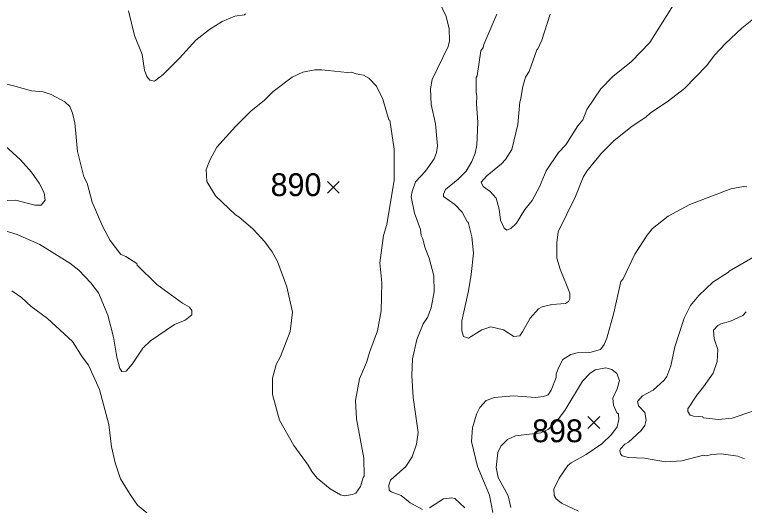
# Model space of a CAD drawing. Extents: x 265.7 to 292.1, y 7676.2 to 7704.2.
# Drawn here: x 270.846 to 273.408, y 7685.609 to 7687.332 of the extents above; entities that cross this region are included whole.
import ezdxf
from ezdxf.enums import TextEntityAlignment as Align

# ---------------------------------------------------------------- set-up
doc = ezdxf.new("R2010")
doc.units = 0
doc.header["$LTSCALE"] = 0.032
doc.layers.add('2', color=7, linetype='Continuous', lineweight=13)
doc.layers.add('21', color=7, linetype='Continuous', lineweight=25)
doc.layers.add('61', color=7, linetype='Continuous')

msp = doc.modelspace()

# ---------------------------------------------------------------- linework, layer by layer
at = {"layer": '2'}
for points in [[(272.2789, 7685.5938), (272.235, 7685.6178), (272.2031, 7685.6433), (272.1688, 7685.6561), (272.1616, 7685.6625), (272.1608, 7685.68), (272.1664, 7685.6968), (272.2199, 7685.7454), (272.2422, 7685.779), (272.2574, 7685.8236), (272.263, 7685.8651), (272.2454, 7685.988), (272.2414, 7686.0646), (272.2438, 7686.1237), (272.259, 7686.1907), (272.2805, 7686.2466), (272.2957, 7686.2689), (272.3084, 7686.3024), (272.3196, 7686.3583), (272.318, 7686.4141), (272.3021, 7686.4772), (272.2869, 7686.5147), (272.2797, 7686.545), (272.2741, 7686.5562), (272.2709, 7686.5769), (272.2502, 7686.6344), (272.239, 7686.6918), (272.2422, 7686.711), (272.2542, 7686.7445), (272.2893, 7686.782), (272.3188, 7686.8259), (272.3276, 7686.8482), (272.3308, 7686.8706), (272.3244, 7686.9488), (272.3084, 7687.0158), (272.3068, 7687.0717), (272.3124, 7687.1036), (272.3683, 7687.2201), (272.3731, 7687.2392), (272.3723, 7687.2823), (272.3611, 7687.3254), (272.3252, 7687.402)], [(273.1654, 7687.3749), (273.0761, 7687.2344), (273.0122, 7687.1674), (272.9468, 7687.1147), (272.9045, 7687.0716), (272.855, 7686.9982), (272.8407, 7686.9623), (272.8239, 7686.9408), (272.7816, 7686.8746), (272.7561, 7686.8474), (272.713, 7686.7828), (272.6891, 7686.7269), (272.6635, 7686.6791), (272.638, 7686.6471), (272.6085, 7686.5993), (272.5885, 7686.5809), (272.575, 7686.5753), (272.5654, 7686.5825), (272.5526, 7686.6104), (272.5478, 7686.6487), (272.5367, 7686.687), (272.5159, 7686.7102), (272.4912, 7686.7285), (272.4848, 7686.7429), (272.5039, 7686.766), (272.5558, 7686.8075), (272.5702, 7686.8235), (272.5925, 7686.8578), (272.6133, 7686.9456), (272.6196, 7687.0254), (272.6228, 7687.031), (272.6308, 7687.0796), (272.6404, 7687.1116), (272.6524, 7687.1315), (272.6795, 7687.2081), (272.6835, 7687.2113), (272.697, 7687.2424), (272.7266, 7687.3334)], [(271.3684, 7687.1219), (271.3373, 7687.098), (271.3214, 7687.1012), (271.311, 7687.1147), (271.303, 7687.1371), (271.2942, 7687.1913), (271.2679, 7687.2584), (271.2463, 7687.3446)], [(271.6533, 7687.331), (271.6198, 7687.3262), (271.5751, 7687.307), (271.5304, 7687.2791), (271.4825, 7687.2424), (271.4251, 7687.1786), (271.3684, 7687.1219)], [(271.6565, 7687.3342), (271.6533, 7687.331)], [(272.796, 7686.3343), (272.7904, 7686.324), (272.78, 7686.3176), (272.7322, 7686.3144), (272.6986, 7686.3056), (272.6859, 7686.2984), (272.6563, 7686.2657), (272.63, 7686.2178), (272.6196, 7686.2043), (272.5989, 7686.2019), (272.5622, 7686.225), (272.5183, 7686.2354), (272.4864, 7686.225), (272.4401, 7686.1963), (272.4225, 7686.2019), (272.417, 7686.221), (272.4162, 7686.2561), (272.4401, 7686.3615), (272.4497, 7686.4189), (272.4569, 7686.4939), (272.4521, 7686.5514), (272.4393, 7686.6032), (272.4361, 7686.6032), (272.4178, 7686.6376), (272.3914, 7686.6647), (272.3523, 7686.6934), (272.3523, 7686.7014), (272.3587, 7686.7174), (272.4042, 7686.7541), (272.4313, 7686.782), (272.4521, 7686.8163), (272.4632, 7686.845), (272.4696, 7686.8738), (272.4728, 7686.9536), (272.468, 7687.019), (272.4696, 7687.0445), (272.4664, 7687.0605), (272.4664, 7687.1107), (272.4704, 7687.1171), (272.4832, 7687.2041), (272.4912, 7687.2161), (272.4936, 7687.2273), (272.5398, 7687.3334)], [(273.4407, 7687.3166), (273.3993, 7687.2839), (273.3418, 7687.2304), (273.3035, 7687.1889), (273.2764, 7687.153), (273.1982, 7687.0724), (273.1423, 7687.0294), (273.0777, 7686.9855), (273.0625, 7686.9711), (273.0146, 7686.94), (272.9516, 7686.8897), (272.9069, 7686.845), (272.855, 7686.782), (272.8423, 7686.7605), (272.8151, 7686.6934)], [(270.7803, 7687.0964), (270.8474, 7687.0804), (270.9064, 7687.0637), (270.9463, 7687.0605), (270.975, 7687.0517), (271.0229, 7687.0254), (271.0405, 7687.0086), (271.0501, 7686.9855), (271.058, 7686.952), (271.0668, 7686.8514), (271.0899, 7686.762), (271.1011, 7686.7397), (271.1187, 7686.6727), (271.1562, 7686.5865), (271.1825, 7686.5386), (271.2192, 7686.4891), (271.2368, 7686.482), (271.2751, 7686.458), (271.2767, 7686.4524), (271.3461, 7686.3838), (271.4363, 7686.3184), (271.4602, 7686.3048), (271.4682, 7686.2928), (271.469, 7686.2777), (271.4458, 7686.2593), (271.4075, 7686.2442), (271.323, 7686.1859), (271.2966, 7686.1604), (271.2591, 7686.1045), (271.2376, 7686.0798), (271.2232, 7686.0782), (271.216, 7686.0894), (271.2057, 7686.1285), (271.1937, 7686.1987), (271.1737, 7686.2769), (271.141, 7686.3551), (271.1139, 7686.3902), (271.0724, 7686.4341), (271.0405, 7686.4588), (270.9351, 7686.525), (270.8561, 7686.5602), (270.8131, 7686.5721)], [(270.7851, 7686.8953), (270.8673, 7686.8219), (270.9064, 7686.7788), (270.9327, 7686.7397), (270.9503, 7686.7062), (270.9543, 7686.6798), (270.9399, 7686.6623), (270.9176, 7686.6623), (270.8506, 7686.6798), (270.7883, 7686.6783)], [(273.4168, 7686.7269), (273.4056, 7686.7285), (273.361, 7686.7197), (273.2173, 7686.6647), (273.1407, 7686.624)], [(272.8151, 7686.6934), (272.7545, 7686.5689), (272.7497, 7686.5306), (272.7505, 7686.4764), (272.7617, 7686.4381), (272.7952, 7686.3535), (272.796, 7686.3343)], [(273.1407, 7686.624), (273.0857, 7686.5809), (273.0673, 7686.5578), (273.0234, 7686.4907), (272.9827, 7686.4046), (272.9747, 7686.395), (272.95, 7686.2849)], [(273.4088, 7685.7718), (273.3849, 7685.7813), (273.3266, 7685.7901), (273.2939, 7685.7877), (273.2748, 7685.7829), (273.2652, 7685.7845), (273.1886, 7685.7654), (273.1311, 7685.7614), (273.0577, 7685.775), (273.0019, 7685.7766), (272.9795, 7685.7821), (272.9731, 7685.7901), (272.9715, 7685.8013), (272.9739, 7685.8077), (272.9891, 7685.8236), (273.0019, 7685.8308), (273.0466, 7685.8715), (273.0585, 7685.8891), (273.0641, 7685.9082), (273.0585, 7685.9346), (273.0362, 7685.9577), (273.033, 7685.9729), (273.0505, 7685.9928), (273.0881, 7686.0136), (273.1263, 7686.0479), (273.1359, 7686.0614), (273.1503, 7686.0981), (273.1646, 7686.1652), (273.1966, 7686.2657), (273.2189, 7686.3104), (273.2484, 7686.3455), (273.2971, 7686.3926), (273.353, 7686.4269), (273.3554, 7686.4309), (273.4376, 7686.4788)], [(271.3102, 7685.5827), (271.2783, 7685.6098), (271.2519, 7685.6465), (271.2184, 7685.7024), (271.2001, 7685.7582), (271.1865, 7685.8141), (271.1769, 7685.8923), (271.145, 7686.0152), (271.1059, 7686.1013), (271.0836, 7686.1301), (271.05, 7686.1843), (270.9615, 7686.2649), (270.9048, 7686.3072), (270.8705, 7686.3383), (270.837, 7686.3615)], [(273.4376, 7685.9393), (273.3657, 7685.9146), (273.3179, 7685.9106), (273.2636, 7685.9162), (273.2628, 7685.9194), (273.2301, 7685.9218), (273.2181, 7685.9258), (273.2101, 7685.9385), (273.2101, 7685.9481), (273.2413, 7685.996), (273.2652, 7686.0247), (273.2987, 7686.0734), (273.3123, 7686.1141), (273.3155, 7686.1556), (273.3027, 7686.1939), (273.2995, 7686.2242), (273.3147, 7686.2402), (273.3258, 7686.2466), (273.3602, 7686.2553), (273.4024, 7686.2753), (273.4152, 7686.2888)], [(272.95, 7686.2849), (272.9261, 7686.1955), (272.9165, 7686.1732), (272.9037, 7686.1556), (272.8662, 7686.146), (272.8215, 7686.1444), (272.7992, 7686.1388), (272.7713, 7686.1205), (272.7553, 7686.0918), (272.7473, 7686.0694), (272.7473, 7686.0582), (272.7306, 7686.0136), (272.7194, 7685.9968), (272.7034, 7685.9904), (272.6747, 7685.988), (272.5981, 7685.9936), (272.5311, 7685.9872), (272.5023, 7685.9768), (272.48, 7685.9521), (272.468, 7685.929), (272.4545, 7685.8811), (272.4505, 7685.8332), (272.4712, 7685.7454), (272.5135, 7685.6449), (272.5255, 7685.5834)], [(272.962, 7685.8843), (272.9676, 7685.9098), (272.9668, 7685.9306), (272.9612, 7685.9338), (272.9492, 7685.9609), (272.946, 7685.9848), (272.962, 7686.0183), (272.9699, 7686.0471), (272.9612, 7686.0718), (272.9436, 7686.0862), (272.9221, 7686.0918), (272.8846, 7686.0846), (272.8662, 7686.0718), (272.8399, 7686.0447), (272.7784, 7685.9417), (272.7553, 7685.9122), (272.7208, 7685.876), (272.6943, 7685.8635), (272.6053, 7685.8528), (272.5765, 7685.8397), (272.5534, 7685.8165), (272.543, 7685.7949), (272.5367, 7685.7415), (272.5438, 7685.7071), (272.5789, 7685.6417), (272.5885, 7685.6018)], [(272.7585, 7685.7039), (272.7888, 7685.7486), (272.8, 7685.7582), (272.8534, 7685.7877), (272.9077, 7685.8252), (272.942, 7685.858), (272.962, 7685.8843)], [(272.8263, 7685.5882), (272.7665, 7685.6162), (272.7481, 7685.6321), (272.7409, 7685.6433), (272.7393, 7685.6656), (272.7585, 7685.7039)], [(272.4265, 7685.6002), (272.3922, 7685.6329), (272.3811, 7685.6353), (272.3523, 7685.6313), (272.3029, 7685.6002)]]:
    msp.add_lwpolyline(points, dxfattribs=at)
msp.add_lwpolyline([(271.9245, 7687.1381), (272.014, 7687.1283), (272.0292, 7687.1299), (272.0459, 7687.1235), (272.0714, 7687.1195), (272.0906, 7687.1084), (272.1169, 7687.0804), (272.1393, 7687.0349), (272.1608, 7686.9623), (272.164, 7686.9607), (272.1784, 7686.8594), (272.1792, 7686.7509), (272.1536, 7686.5945), (272.1417, 7686.5562), (272.1289, 7686.4604), (272.1353, 7686.3902), (272.1329, 7686.2912), (272.1201, 7686.221), (272.093, 7686.1492), (272.0818, 7686.1109), (272.0571, 7686.0535), (272.0435, 7685.9769), (272.0467, 7685.913), (272.073, 7685.7742), (272.0738, 7685.7111), (272.0698, 7685.7063), (272.0603, 7685.6752), (272.0443, 7685.6521), (272.0323, 7685.6465), (272.0044, 7685.6425), (271.9909, 7685.6457), (271.9541, 7685.6672), (271.9087, 7685.7047), (271.8895, 7685.7279), (271.8767, 7685.7502), (271.8265, 7685.8189), (271.7762, 7685.9082), (271.7515, 7685.9976), (271.7515, 7686.0551), (271.7642, 7686.1029), (271.7794, 7686.1317), (271.8137, 7686.2194), (271.8225, 7686.2865), (271.8025, 7686.3758), (271.7698, 7686.4652), (271.7507, 7686.4987), (271.7251, 7686.5338), (271.6844, 7686.5785), (271.6342, 7686.6216), (271.6214, 7686.6288), (271.552, 7686.695), (271.5208, 7686.7461), (271.5192, 7686.7876), (271.532, 7686.8211), (271.5568, 7686.8658), (271.6214, 7686.9392), (271.6757, 7686.9927), (271.7235, 7687.0317), (271.7539, 7687.0621), (271.8209, 7687.1123), (271.8584, 7687.1299), (271.9007, 7687.1379)], close=True, dxfattribs=at)
at = {"layer": '21'}
for p, q in [((271.9452, 7686.7457), (271.9864, 7686.7045)), ((271.9864, 7686.7457), (271.9452, 7686.7045)), ((272.8594, 7685.9202), (272.9006, 7685.879)), ((272.9006, 7685.9202), (272.8594, 7685.879))]:
    msp.add_line(p, q, dxfattribs=at)

# ---------------------------------------------------------------- texts
at = {"layer": '61'}
for s, p in [('890', (271.8345, 7686.6946)), ('898', (272.7521, 7685.8305))]:
    msp.add_text(s, height=0.08, dxfattribs=at).set_placement(p, align=Align.CENTER)

doc.saveas('drawing.dxf')
